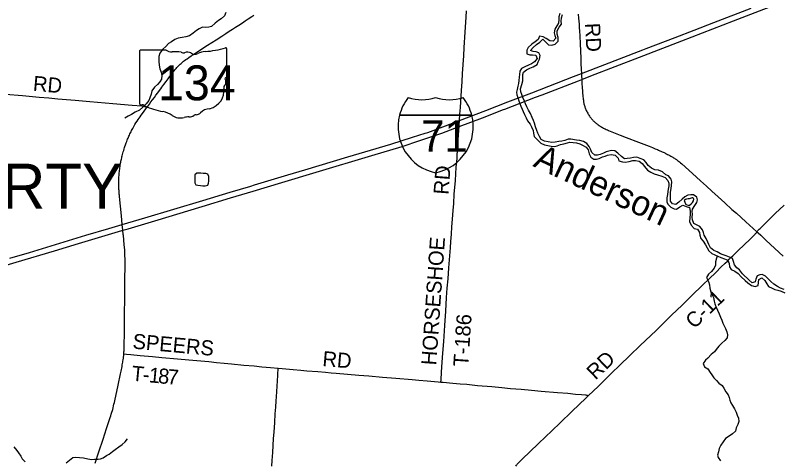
# Model space of a CAD drawing. Extents: x 1442749 to 1756758, y 235267 to 677782.
# Drawn here: x 1596490 to 1611806, y 554957 to 563845 of the extents above; entities that cross this region are included whole.
import ezdxf

# ---------------------------------------------------------------- set-up
doc = ezdxf.new("R2010")
doc.units = 0
for name, color, linetype in [('GM_X_County_Road', 7, 'Continuous'), ('GM_X_County_Road_Text', 7, 'Continuous'), ('GM_X_Interstate_Location', 7, 'Continuous'), ('GM_X_Interstate_Route', 7, 'Continuous'), ('GM_X_Interstate_Shield', 7, 'Continuous'), ('GM_X_Major_River', 7, 'Continuous'), ('GM_X_Major_River_Text', 7, 'Continuous'), ('GM_X_Minor_Lake', 7, 'Continuous'), ('GM_X_Minor_River', 7, 'Continuous'), ('GM_X_State_Location', 7, 'Continuous'), ('GM_X_State_Route', 7, 'Continuous'), ('GM_X_State_Shield', 7, 'Continuous'), ('GM_X_Township_Road', 7, 'Continuous'), ('GM_X_Township_Road_Text', 7, 'Continuous'), ('GM_X_Township_Text', 7, 'Continuous')]:
    doc.layers.add(name, color=color, linetype=linetype)

msp = doc.modelspace()

# ---------------------------------------------------------------- linework, layer by layer
at = {"layer": 'GM_X_County_Road'}
for points in [[(1607736, 563869), (1607740, 563844), (1607743, 563818), (1607746, 563798), (1607748, 563775), (1607751, 563745), (1607754, 563716), (1607756, 563683), (1607758, 563654), (1607761, 563603), (1607765, 563532), (1607769, 563439), (1607777, 563278), (1607790, 562993), (1607795, 562892), (1607800, 562767), (1607806, 562684), (1607808, 562640), (1607812, 562568), (1607815, 562502), (1607820, 562388), (1607822, 562354), (1607824, 562324), (1607827, 562284), (1607830, 562251), (1607833, 562220), (1607836, 562193), (1607839, 562172), (1607842, 562151), (1607845, 562131), (1607848, 562113), (1607852, 562096), (1607855, 562080), (1607860, 562062), (1607864, 562047), (1607870, 562027), (1607875, 562012), (1607880, 561999), (1607886, 561981), (1607893, 561965), (1607901, 561947), (1607909, 561928), (1607918, 561910), (1607929, 561891), (1607939, 561873), (1607946, 561863), (1607954, 561851), (1607964, 561835), (1607974, 561821), (1607986, 561806), (1607997, 561792), (1608008, 561778), (1608020, 561765), (1608030, 561754), (1608040, 561743), (1608051, 561732), (1608062, 561721), (1608073, 561711), (1608085, 561701), (1608096, 561692), (1608109, 561682), (1608125, 561670), (1608141, 561658), (1608155, 561648), (1608168, 561640), (1608181, 561632), (1608194, 561624), (1608209, 561615), (1608227, 561604), (1608244, 561595), (1608259, 561587), (1608277, 561578), (1608297, 561569), (1608322, 561558), (1608347, 561547), (1608375, 561536), (1608410, 561521), (1608576, 561456), (1608701, 561408), (1608946, 561314), (1609156, 561231), (1609222, 561206), (1609277, 561183), (1609322, 561165), (1609345, 561156), (1609372, 561144), (1609394, 561135), (1609416, 561124), (1609438, 561115), (1609455, 561107), (1609470, 561099), (1609487, 561091), (1609507, 561081), (1609525, 561071), (1609546, 561060), (1609569, 561047), (1609592, 561034), (1609614, 561022), (1609631, 561012), (1609646, 561003), (1609661, 560993), (1609675, 560983), (1609689, 560974), (1609702, 560965), (1609718, 560953), (1609732, 560943), (1609746, 560932), (1609762, 560919), (1609785, 560900), (1609809, 560879), (1610021, 560687), (1610181, 560542), (1610301, 560434), (1610411, 560336), (1610537, 560222), (1610668, 560102), (1610812, 559973), (1610900, 559894), (1611090, 559723), (1611312, 559523)], [(1611312, 559523), (1611318, 559531), (1611324, 559539), (1611331, 559548), (1611338, 559557), (1611346, 559565), (1611359, 559579), (1611373, 559594), (1611393, 559613), (1611434, 559653), (1611678, 559887), (1611853, 560055)], [(1607937, 556248), (1608142, 556447), (1608407, 556702), (1608571, 556862), (1608772, 557055), (1608980, 557256), (1609295, 557558), (1609475, 557735), (1609603, 557858), (1609816, 558062), (1609991, 558231), (1610080, 558318), (1610160, 558395), (1610237, 558471), (1610350, 558581), (1610494, 558720), (1610592, 558817), (1610676, 558898), (1610720, 558941), (1610759, 558979), (1610793, 559012), (1610829, 559046), (1610867, 559083), (1610925, 559138), (1611067, 559275), (1611160, 559363), (1611207, 559408), (1611235, 559435), (1611252, 559452), (1611270, 559470), (1611278, 559479), (1611286, 559490), (1611294, 559500), (1611303, 559512), (1611312, 559523)], [(1611312, 559523), (1611336, 559502), (1611387, 559456), (1611498, 559353), (1611839, 559037)], [(1606495, 554845), (1606507, 554866), (1606513, 554877), (1606519, 554885), (1606524, 554892), (1606530, 554899), (1606538, 554908), (1606548, 554917), (1606560, 554929), (1606585, 554953), (1606630, 554997), (1606767, 555127), (1606952, 555304), (1607080, 555426), (1607219, 555561), (1607371, 555706), (1607620, 555944), (1607890, 556202), (1607937, 556248)]]:
    msp.add_lwpolyline(points, dxfattribs=at)
at = {"layer": 'GM_X_Interstate_Route'}
for points in [[(1607018, 562262), (1607744, 562541), (1607812, 562568), (1607992, 562639), (1608966, 563012), (1609811, 563337), (1610846, 563737), (1611452, 563970), (1612264, 564281), (1613442, 564736), (1614263, 565052), (1614823, 565267), (1615558, 565551)], [(1596381, 558999), (1596775, 559113), (1597117, 559216), (1597902, 559456), (1598361, 559591), (1598628, 559670), (1599075, 559803), (1600238, 560152), (1600782, 560313), (1601196, 560439), (1601267, 560461), (1601938, 560661), (1602278, 560760), (1603132, 561019), (1603475, 561120), (1603997, 561276), (1604426, 561411), (1604679, 561493), (1604732, 561510), (1605034, 561620), (1605368, 561746), (1605893, 561946), (1606336, 562119), (1606813, 562297), (1607647, 562623), (1607806, 562684), (1609031, 563155), (1609098, 563181), (1609680, 563405), (1610056, 563552), (1610451, 563703), (1611199, 563989)], [(1606274, 561975), (1606886, 562211), (1607018, 562262)], [(1598621, 559551), (1598640, 559557), (1598742, 559587), (1599276, 559746), (1600225, 560031), (1600791, 560200), (1601244, 560336), (1601819, 560508), (1602504, 560713), (1603617, 561045), (1604223, 561229), (1604575, 561344), (1604851, 561439), (1605012, 561497), (1605360, 561625), (1605829, 561801), (1606244, 561964), (1606274, 561975)], [(1591753, 557379), (1592033, 557502), (1592288, 557607), (1592557, 557711), (1592879, 557825), (1593173, 557920), (1593870, 558128), (1594316, 558263), (1594778, 558401), (1596504, 558918), (1597271, 559148), (1597752, 559290), (1598621, 559551)]]:
    msp.add_lwpolyline(points, dxfattribs=at)
at = {"layer": 'GM_X_Interstate_Shield'}
for p, q in [((1604169, 561852), (1605612, 561852)), ((1605612, 561852), (1604169, 561852)), ((1605612, 561852), (1604169, 561852))]:
    msp.add_line(p, q, dxfattribs=at)
for centre, start, end in [((1605078, 561622), 141.669, 165.8066), ((1604616, 563100), 253.0091, 286.9909), ((1605164, 563100), 253.0091, 286.9909), ((1604703, 561622), 14.1934, 38.331), ((1605078, 561622), 165.8066, 258.463), ((1604703, 561622), 281.537, 14.1934)]:
    msp.add_arc(centre, 938, start, end, dxfattribs=at)
at = {"layer": 'GM_X_Major_River'}
for points in [[(1607371, 563879), (1607355, 563815), (1607351, 563765), (1607347, 563687), (1607311, 563637), (1607271, 563569), (1607259, 563493), (1607271, 563440), (1607289, 563388), (1607242, 563328), (1607172, 563334), (1607102, 563385), (1607039, 563415), (1606967, 563427), (1606940, 563365), (1606880, 563317), (1606810, 563267), (1606742, 563201), (1606714, 563147), (1606710, 563079), (1606774, 563057), (1606828, 563055), (1606890, 563049), (1606916, 562982), (1606864, 562916), (1606804, 562880), (1606747, 562849), (1606675, 562817), (1606607, 562783), (1606571, 562729), (1606565, 562665), (1606559, 562614), (1606555, 562544), (1606549, 562486), (1606531, 562430), (1606517, 562368), (1606508, 562310), (1606512, 562260), (1606530, 562206), (1606550, 562142), (1606570, 562084), (1606592, 562034), (1606622, 561976), (1606642, 561925), (1606668, 561869), (1606700, 561801), (1606725, 561739), (1606779, 561671), (1606809, 561621), (1606841, 561549), (1606845, 561497), (1606857, 561430), (1606919, 561364), (1606993, 561292), (1607067, 561262), (1607135, 561246), (1607197, 561236), (1607267, 561226), (1607319, 561244), (1607387, 561269), (1607455, 561281), (1607523, 561303), (1607573, 561313), (1607639, 561309), (1607703, 561301), (1607771, 561281), (1607827, 561257), (1607901, 561211), (1607937, 561158), (1607959, 561082)], [(1609582, 560251), (1609586, 560317), (1609598, 560387), (1609602, 560449), (1609612, 560519), (1609598, 560577), (1609544, 560643), (1609490, 560665), (1609426, 560722), (1609346, 560752), (1609272, 560760), (1609204, 560796), (1609135, 560846), (1609097, 560906), (1609051, 560963), (1608979, 560989), (1608909, 561015), (1608845, 561009), (1608783, 560995), (1608717, 560987), (1608667, 560981), (1608603, 561031), (1608531, 561095), (1608469, 561142), (1608403, 561146), (1608349, 561136), (1608299, 561120), (1608243, 561092), (1608175, 561066), (1608123, 561056), (1608073, 561052), (1608015, 561108), (1607985, 561172), (1607961, 561225), (1607911, 561289), (1607843, 561329), (1607775, 561345), (1607705, 561353), (1607589, 561377), (1607537, 561371), (1607469, 561349), (1607409, 561336), (1607355, 561330), (1607279, 561314), (1607213, 561308), (1607141, 561322), (1607067, 561334), (1607001, 561368), (1606963, 561430), (1606933, 561494), (1606915, 561545), (1606887, 561619), (1606863, 561691), (1606844, 561747), (1606822, 561809), (1606784, 561885), (1606746, 561955), (1606714, 562021), (1606688, 562078), (1606666, 562134), (1606636, 562208), (1606614, 562266), (1606596, 562316), (1606589, 562380), (1606613, 562464), (1606631, 562536), (1606635, 562598), (1606633, 562664), (1606649, 562714), (1606705, 562760), (1606773, 562788), (1606839, 562818), (1606918, 562862), (1606942, 562916), (1606964, 562968), (1606982, 563042), (1606952, 563097), (1606900, 563117), (1606840, 563121), (1606786, 563141), (1606836, 563205), (1606906, 563261), (1606970, 563313), (1607034, 563369), (1607144, 563258), (1607212, 563248), (1607282, 563270), (1607336, 563332), (1607341, 563402), (1607319, 563470), (1607321, 563535), (1607359, 563609), (1607407, 563671), (1607399, 563731), (1607403, 563793), (1607423, 563861)], [(1607959, 561082), (1607989, 561014), (1608054, 560974), (1608104, 560974), (1608157, 560988), (1608225, 561020), (1608275, 561034), (1608327, 561052), (1608401, 561068), (1608479, 561056), (1608541, 560993), (1608553, 560943), (1608627, 560919), (1608687, 560917), (1608757, 560931), (1608829, 560951), (1608885, 560951), (1608955, 560933), (1609021, 560886), (1609064, 560828), (1609126, 560758), (1609188, 560712), (1609256, 560682), (1609326, 560662), (1609408, 560638), (1609476, 560609), (1609532, 560547), (1609552, 560497), (1609550, 560443), (1609540, 560379), (1609532, 560327), (1609524, 560271), (1609511, 560201), (1609509, 560125), (1609533, 560075), (1609591, 560014), (1609657, 559986), (1609707, 559980), (1609771, 560026), (1609833, 560058), (1609897, 560030), (1609963, 560008), (1609979, 559938), (1609975, 559874), (1609969, 559802), (1609965, 559730), (1609997, 559657), (1610057, 559589), (1610121, 559577), (1610164, 559509), (1610168, 559457), (1610192, 559391), (1610234, 559339), (1610286, 559268), (1610314, 559208), (1610348, 559142), (1610410, 559092), (1610470, 559066), (1610532, 559036), (1610590, 559012), (1610662, 558988), (1610732, 558957), (1610757, 558891), (1610765, 558825), (1610795, 558775), (1610871, 558741), (1610937, 558691), (1610997, 558625), (1611077, 558550), (1611129, 558508), (1611201, 558456), (1611275, 558432), (1611335, 558456), (1611343, 558510), (1611349, 558572), (1611411, 558604), (1611467, 558554), (1611509, 558486), (1611541, 558436), (1611613, 558399), (1611671, 558375), (1611727, 558357), (1611793, 558337), (1611871, 558305)], [(1611853, 558375), (1611785, 558403), (1611725, 558431), (1611649, 558481), (1611589, 558532), (1611527, 558592), (1611485, 558642), (1611419, 558672), (1611369, 558668), (1611319, 558644), (1611289, 558578), (1611273, 558528), (1611217, 558508), (1611153, 558560), (1611025, 558689), (1610963, 558765), (1610913, 558803), (1610861, 558863), (1610846, 558935), (1610826, 558989), (1610764, 559019), (1610694, 559042), (1610636, 559062), (1610584, 559086), (1610514, 559122), (1610448, 559154), (1610386, 559206), (1610348, 559270), (1610332, 559320), (1610294, 559389), (1610256, 559461), (1610244, 559513), (1610225, 559565), (1610173, 559629), (1610101, 559665), (1610047, 559691), (1610021, 559762), (1610017, 559816), (1610023, 559878), (1610019, 559928), (1610021, 559980), (1610067, 560048), (1610109, 560108), (1610122, 560166), (1610110, 560218), (1610044, 560260), (1609990, 560266), (1609930, 560256), (1609872, 560220), (1609819, 560174), (1609751, 560114), (1609691, 560070), (1609621, 560081), (1609585, 560135), (1609581, 560185), (1609582, 560251)], [(1609994, 560198), (1609958, 560184), (1609934, 560180), (1609904, 560178), (1609882, 560172), (1609859, 560148), (1609869, 560114), (1609891, 560068), (1609935, 560054), (1609959, 560048), (1609997, 560080), (1610021, 560110), (1610045, 560140)], [(1610045, 560140), (1610049, 560179), (1610042, 560191), (1610023, 560202), (1610019, 560203), (1609994, 560198)]]:
    msp.add_lwpolyline(points, dxfattribs=at)
at = {"layer": 'GM_X_Minor_Lake'}
for points in [[(1600356, 560552), (1600356, 560588), (1600355, 560632), (1600336, 560678), (1600294, 560687), (1600246, 560690), (1600200, 560696), (1600158, 560697), (1600116, 560692), (1600079, 560662), (1600074, 560618), (1600077, 560570), (1600075, 560524)], [(1600075, 560524), (1600074, 560500), (1600094, 560461), (1600140, 560453), (1600188, 560446), (1600234, 560441), (1600286, 560444), (1600334, 560456), (1600353, 560497), (1600355, 560537), (1600356, 560552)]]:
    msp.add_lwpolyline(points, dxfattribs=at)
at = {"layer": 'GM_X_Minor_River'}
for points in [[(1600700, 563900), (1600671, 563835), (1600605, 563776), (1600549, 563740), (1600482, 563689), (1600412, 563622), (1600358, 563607), (1600294, 563600), (1600230, 563607), (1600163, 563578), (1600111, 563541), (1600046, 563490), (1599973, 563439), (1599898, 563414), (1599822, 563401), (1599745, 563392), (1599677, 563361), (1599610, 563318), (1599553, 563285), (1599500, 563226), (1599435, 563167), (1599377, 563093), (1599360, 563021), (1599357, 562971), (1599360, 562921), (1599367, 562849), (1599378, 562779)], [(1599378, 562779), (1599403, 562710), (1599416, 562642), (1599413, 562570), (1599376, 562516), (1599329, 562465), (1599268, 562411), (1599218, 562336), (1599203, 562272), (1599178, 562198), (1599157, 562145), (1599104, 562077), (1599040, 562010), (1598971, 561955), (1598886, 561914), (1598811, 561865), (1598745, 561834), (1598678, 561793)], [(1610517, 559043), (1610500, 558996), (1610481, 558928), (1610483, 558862), (1610458, 558796), (1610405, 558733), (1610342, 558678), (1610303, 558616), (1610344, 558535), (1610362, 558469), (1610371, 558400), (1610388, 558330), (1610407, 558278), (1610442, 558211), (1610457, 558138), (1610472, 558084), (1610491, 558032), (1610522, 557961), (1610559, 557890), (1610582, 557824), (1610611, 557759), (1610630, 557699), (1610655, 557648), (1610682, 557598), (1610707, 557531), (1610726, 557466), (1610717, 557410), (1610668, 557353), (1610607, 557304), (1610552, 557239), (1610499, 557179), (1610462, 557128), (1610397, 557073), (1610333, 557004), (1610282, 556962), (1610237, 556899), (1610262, 556832), (1610327, 556787), (1610376, 556720), (1610410, 556668), (1610453, 556611), (1610502, 556558), (1610547, 556507), (1610618, 556456), (1610647, 556403), (1610692, 556330), (1610735, 556273), (1610758, 556217), (1610772, 556167), (1610791, 556110), (1610824, 556060), (1610861, 555993), (1610896, 555924), (1610917, 555868), (1610946, 555805), (1610947, 555737), (1610932, 555681), (1610896, 555609), (1610881, 555547), (1610822, 555494), (1610755, 555449), (1610684, 555398), (1610637, 555331), (1610588, 555263), (1610555, 555202), (1610540, 555136), (1610524, 555068), (1610537, 555018), (1610586, 554951)], [(1597503, 554911), (1597573, 554970), (1597640, 555021), (1597702, 555026), (1597774, 555021), (1597850, 555016), (1597940, 554992), (1598020, 554983), (1598070, 554988), (1598144, 554989), (1598194, 554996), (1598247, 555016), (1598312, 555061), (1598362, 555088), (1598431, 555139), (1598484, 555180), (1598557, 555235), (1598626, 555282), (1598685, 555335), (1598734, 555393)], [(1596457, 555235), (1596518, 555163), (1596551, 555113), (1596598, 555044), (1596623, 554991), (1596686, 554934)]]:
    msp.add_lwpolyline(points, dxfattribs=at)
at = {"layer": 'GM_X_State_Route'}
for points in [[(1598593, 560893), (1598597, 560915), (1598601, 560935), (1598605, 560952), (1598609, 560973), (1598615, 560999), (1598620, 561020), (1598625, 561041), (1598632, 561069), (1598640, 561097), (1598648, 561123), (1598655, 561148), (1598664, 561179), (1598672, 561205), (1598680, 561229), (1598690, 561258), (1598698, 561282), (1598706, 561303), (1598716, 561330), (1598725, 561352), (1598734, 561375), (1598742, 561394), (1598750, 561411), (1598759, 561434), (1598770, 561457), (1598780, 561478), (1598791, 561502), (1598802, 561522), (1598814, 561546), (1598824, 561566), (1598835, 561586), (1598850, 561613), (1598864, 561637), (1598880, 561664), (1598901, 561699), (1598925, 561736), (1598944, 561765), (1598964, 561794), (1598982, 561819), (1599006, 561851), (1599030, 561884), (1599065, 561932), (1599099, 561978), (1599121, 562007), (1599130, 562020), (1599169, 562071), (1599201, 562116), (1599234, 562161), (1599268, 562207), (1599299, 562250), (1599337, 562301), (1599370, 562347), (1599395, 562380), (1599418, 562409), (1599459, 562464), (1599503, 562522), (1599543, 562577), (1599574, 562619), (1599600, 562654), (1599616, 562674), (1599634, 562699), (1599652, 562722), (1599665, 562738), (1599678, 562755), (1599701, 562782), (1599719, 562802), (1599736, 562821), (1599752, 562838), (1599769, 562855), (1599786, 562871), (1599802, 562886), (1599817, 562900), (1599833, 562913), (1599852, 562928), (1599872, 562944), (1599896, 562961), (1599922, 562980), (1599960, 563006), (1600004, 563035), (1600053, 563067), (1600174, 563147), (1600331, 563248), (1600502, 563358), (1600617, 563433), (1600697, 563484), (1600764, 563527), (1600828, 563569), (1600889, 563609), (1600956, 563652), (1601027, 563698), (1601081, 563733), (1601142, 563773), (1601218, 563822), (1601256, 563847)], [(1598648, 559474), (1598640, 559557), (1598628, 559670), (1598612, 559843), (1598592, 560036), (1598572, 560231), (1598570, 560256), (1598568, 560278), (1598566, 560304), (1598564, 560329), (1598562, 560349), (1598561, 560369), (1598560, 560391), (1598559, 560418), (1598558, 560440), (1598558, 560460), (1598557, 560480), (1598557, 560499), (1598557, 560519), (1598558, 560543), (1598559, 560572), (1598559, 560598), (1598561, 560623), (1598562, 560652), (1598564, 560676), (1598566, 560702), (1598569, 560727), (1598572, 560751), (1598575, 560774), (1598579, 560803), (1598583, 560831), (1598587, 560858), (1598593, 560891), (1598593, 560893)], [(1598680, 558540), (1598681, 558613), (1598683, 558803), (1598683, 558957), (1598680, 559072), (1598678, 559116), (1598675, 559164), (1598672, 559214), (1598668, 559269), (1598651, 559448), (1598648, 559474)], [(1598084, 554908), (1598157, 555130), (1598243, 555388), (1598314, 555599), (1598388, 555820), (1598397, 555850), (1598408, 555883), (1598420, 555924), (1598430, 555957), (1598436, 555981), (1598445, 556014), (1598454, 556050), (1598461, 556082), (1598470, 556121), (1598478, 556153), (1598543, 556461), (1598592, 556692), (1598603, 556741), (1598610, 556775), (1598616, 556803), (1598622, 556834), (1598628, 556868), (1598634, 556898), (1598638, 556924), (1598641, 556946), (1598645, 556967), (1598649, 557000), (1598652, 557026), (1598655, 557057), (1598658, 557081), (1598658, 557088), (1598659, 557104), (1598661, 557129), (1598663, 557152), (1598665, 557183), (1598666, 557222), (1598668, 557261), (1598668, 557309), (1598670, 557452), (1598673, 557845), (1598677, 558232), (1598679, 558419), (1598680, 558540)]]:
    msp.add_lwpolyline(points, dxfattribs=at)
at = {"layer": 'GM_X_State_Shield'}
for p, q in [((1598974, 563132), (1598974, 562075)), ((1599501, 563150), (1598992, 563150)), ((1600715, 562624), (1600715, 563176)), ((1600714, 562624), (1600715, 562624))]:
    msp.add_line(p, q, dxfattribs=at)
for centre, major_axis, start_param, end_param in [((1600095, 564591), (1845, 0), 4.814394, 5.042369), ((1600695, 563179), (19.4, 0), 6.141152, 7.989035), ((1598994, 563134), (20.2, 0), 1.712693, 3.28349), ((1599623, 563273), (196, 0), 4.042523, 4.731795), ((1599687, 562557), (702, 0), 1.404758, 1.657858), ((1599847, 563140), (56.4, 0), 3.836095, 5.185415), ((1599930, 563018), (117, 0), 0.950623, 2.079405), ((1600081, 563185), (141, 0), 4.081561, 5.145723), ((1600330, 562827), (371, 0), 1.699011, 2.107814), ((1600710, 562583), (30, 0), 1.883978, 3.671073), ((1600519, 562513), (180, 0), 5.934695, 6.695948), ((1600694, 562621), (20.7, 0), 5.05454, 6.418171), ((1600784, 562392), (131, 0), 2.387724, 3.262537), ((1600198, 562322), (462, 0), 5.101752, 6.440018), ((1598995, 562073), (20.3, 0), 3.00124, 4.508301), ((1598998, 562181), (155, 0), 4.665946, 4.897461), ((1599029, 562014), (56, 0), 0.519207, 1.627899), ((1599736, 562964), (1333, 0), 4.195997, 4.488961), ((1600393, 561779), (253, 0), 1.647645, 2.488434), ((1599339, 561601), (417, 0), 0.823519, 1.323587), ((1599790, 562009), (265, 0), 4.026481, 4.996735), ((1599943, 561644), (217, 0), 1.495662, 1.94098), ((1599962, 561930), (141, 0), 4.691044, 5.507374), ((1600089, 561828), (39.7, 0), 1.147584, 2.315152), ((1600072, 561973), (149, 0), 4.937069, 5.64225)]:
    msp.add_ellipse(centre, major_axis=major_axis, ratio=0.8, start_param=start_param, end_param=end_param, dxfattribs=at)
at = {"layer": 'GM_X_Township_Road'}
for points in [[(1604996, 556526), (1604999, 556568), (1605009, 556721), (1605014, 556820), (1605027, 557013), (1605039, 557180), (1605051, 557333), (1605059, 557445), (1605073, 557654), (1605091, 557942), (1605110, 558214), (1605123, 558397), (1605138, 558587), (1605155, 558809), (1605179, 559127), (1605184, 559205), (1605194, 559333), (1605206, 559480), (1605216, 559621), (1605227, 559775), (1605240, 559948), (1605251, 560092), (1605263, 560275), (1605284, 560550), (1605303, 560815), (1605317, 560985), (1605322, 561064), (1605332, 561208), (1605334, 561237), (1605342, 561362), (1605355, 561548), (1605360, 561625), (1605363, 561659), (1605368, 561746), (1605376, 561872), (1605384, 562003), (1605407, 562343), (1605418, 562517), (1605429, 562684), (1605451, 563034), (1605461, 563205), (1605481, 563512), (1605500, 563807), (1605509, 563938)], [(1596292, 562273), (1596635, 562244), (1596965, 562215), (1597158, 562198), (1597338, 562182), (1597514, 562165), (1597684, 562150), (1597982, 562126), (1598440, 562086), (1598825, 562052), (1599015, 562036), (1599055, 562031), (1599072, 562027), (1599088, 562022), (1599111, 562011), (1599121, 562007)], [(1598658, 557088), (1598712, 557083), (1598800, 557075), (1598987, 557058), (1599231, 557034), (1599418, 557017), (1599734, 556988), (1599960, 556967), (1600195, 556947), (1600359, 556933), (1600509, 556917), (1600665, 556902), (1600812, 556889), (1601057, 556866), (1601266, 556847), (1601417, 556833), (1601590, 556817), (1601744, 556804)], [(1601617, 554848), (1601624, 554963), (1601634, 555120), (1601652, 555398), (1601660, 555529), (1601673, 555722), (1601685, 555893), (1601693, 556023), (1601702, 556148), (1601708, 556230), (1601735, 556658), (1601739, 556710), (1601742, 556766), (1601744, 556804)], [(1601744, 556804), (1601822, 556797), (1602044, 556776), (1602194, 556763), (1602315, 556753), (1602534, 556735), (1602688, 556722), (1602799, 556713), (1602904, 556704), (1603129, 556684), (1603358, 556664), (1603557, 556648), (1603825, 556625), (1604097, 556603), (1604424, 556576), (1604555, 556566), (1604724, 556551), (1604940, 556531), (1604996, 556526)], [(1604996, 556526), (1605038, 556522), (1605231, 556505), (1605381, 556492), (1605515, 556481), (1605724, 556460), (1606012, 556434), (1606211, 556417), (1606387, 556400), (1606597, 556381), (1606809, 556362), (1606998, 556346), (1607325, 556318), (1607531, 556301), (1607685, 556287), (1607806, 556277), (1607884, 556269), (1607894, 556268), (1607903, 556266), (1607911, 556265), (1607916, 556263), (1607923, 556259), (1607929, 556254), (1607937, 556248)]]:
    msp.add_lwpolyline(points, dxfattribs=at)

# ---------------------------------------------------------------- texts
at = {"layer": 'GM_X_County_Road_Text'}
for s, rotation, p in [('RD', 272.9055, (1607875, 563687)), ('C-11', 44.0343, (1610059, 557574)), ('RD', 43.9586, (1608084, 556556))]:
    msp.add_text(s, height=300, rotation=rotation, dxfattribs=at).set_placement(p)
at = {"layer": 'GM_X_Interstate_Location'}
for s in ['-', '.', ',']:
    msp.add_text(s, height=1, dxfattribs=at).set_placement((1604890, 561453))
msp.add_text('71', height=1, rotation=0, dxfattribs=at).set_placement((1604686, 561246))
at = {"layer": 'GM_X_Interstate_Shield'}
msp.add_text('71', height=625, dxfattribs=at).set_placement((1604602, 561126))
at = {"layer": 'GM_X_Major_River_Text'}
msp.add_text('Anderson', height=500, rotation=335.0263, dxfattribs=at).set_placement((1606817, 560840))
at = {"layer": 'GM_X_State_Location'}
msp.add_text('134', height=1, rotation=0, dxfattribs=at).set_placement((1599472, 562461))
for s in ['s', 'r']:
    msp.add_text(s, height=1, dxfattribs=at).set_placement((1599825, 562533))
at = {"layer": 'GM_X_State_Shield'}
msp.add_text('134', height=696.1, dxfattribs=at).set_placement((1599341, 562150))
at = {"layer": 'GM_X_Township_Road_Text'}
for s, rotation, p in [('RD', 355.0752, (1596834, 562340)), ('RD', 85.6003, (1605145, 560259)), ('HORSESHOE', 86.0473, (1604902, 556854)), ('T-186', 86.1107, (1605540, 556828)), ('SPEERS', 354.8224, (1598824, 557195)), ('RD', 355.0816, (1602619, 556847)), ('T', 354.5922, (1598803, 556555)), ('1', 354.6273, (1599149, 556522)), ('8', 354.6801, (1599333, 556505)), ('7', 354.9288, (1599519, 556488)), ('-', 354.618, (1599026, 556534))]:
    msp.add_text(s, height=300, rotation=rotation, dxfattribs=at).set_placement(p)
at = {"layer": 'GM_X_Township_Text'}
msp.add_text('LIBERTY', height=900, rotation=0, dxfattribs=at).set_placement((1593612, 559985))

doc.saveas('drawing.dxf')
